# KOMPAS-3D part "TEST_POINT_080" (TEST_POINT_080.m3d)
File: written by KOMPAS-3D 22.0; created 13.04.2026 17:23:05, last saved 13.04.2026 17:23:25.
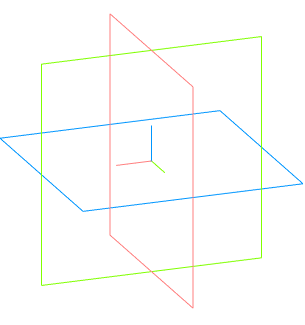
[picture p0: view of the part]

Document properties: Автор: Andrey; Полное имя файла: C:\Users\User1\Documents\Работа\Корпуса\Корпус Repka Pi 5\Конструкторская документация\3д модель\Repka_5_3D\TEST_POINT_080.m3d

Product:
- Part/product: TEST_POINT_080
    Комментарий: TEST_POINT_080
